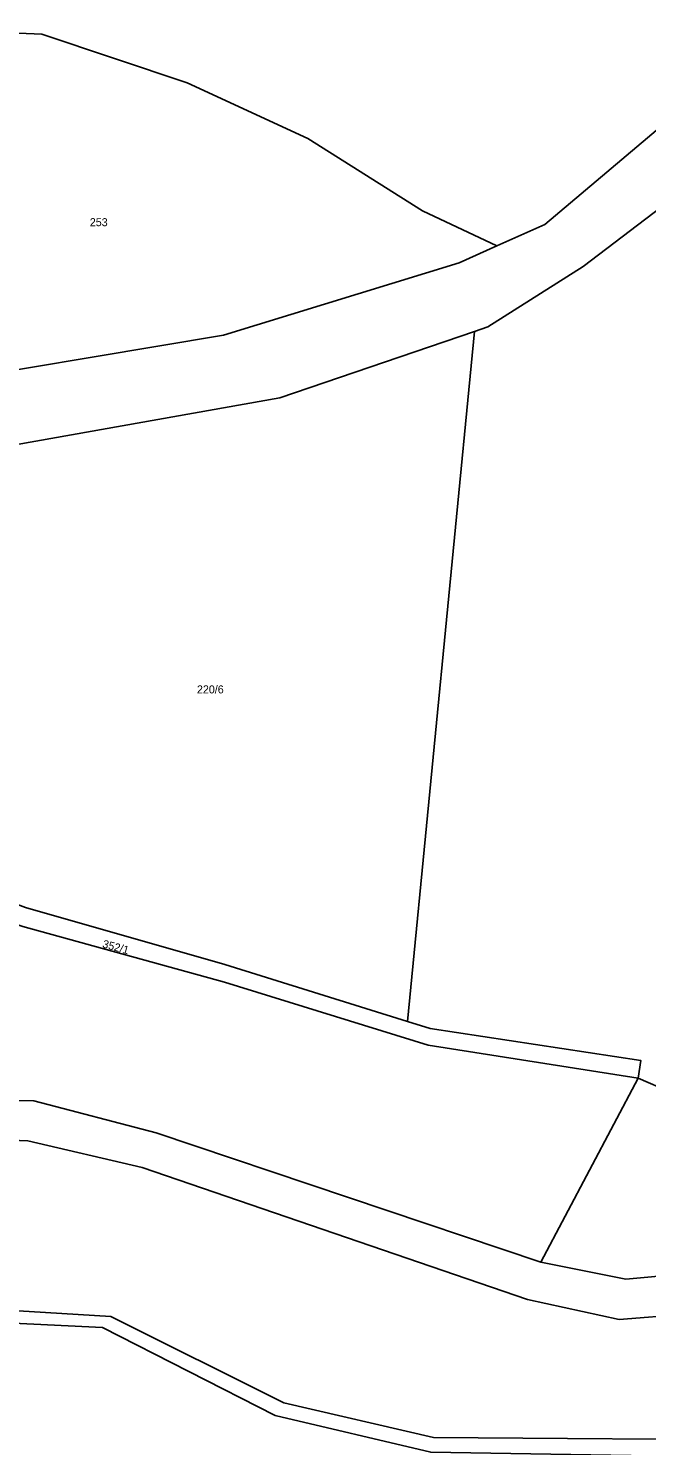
# Model space of a CAD drawing. Extents: x -880531 to -877616, y -1023932 to -1021350.
# Drawn here: x -878561.2 to -878429.8, y -1022509.8 to -1022208.6 of the extents above; entities that cross this region are included whole.
import ezdxf

# ---------------------------------------------------------------- set-up
doc = ezdxf.new("R2010")
doc.units = 0
doc.layers.add('Hranice parcel', color=7, linetype='Continuous')
doc.layers.add('Parcelní čísla', color=7, linetype='Continuous')

msp = doc.modelspace()

# ---------------------------------------------------------------- linework, layer by layer
at = {"layer": 'Hranice parcel'}
for p, q in [((-878466.42, -1022273.02), (-878480.63, -1022419.65)), ((-878452.29, -1022470.77), (-878431.64, -1022431.71))]:
    msp.add_line(p, q, dxfattribs=at)
for points in [[(-878461.63, -1022254.79), (-878477.42, -1022247.38), (-878501.8, -1022232.02), (-878527.45, -1022220.17), (-878558.36, -1022209.87), (-878586.62, -1022208.6)], [(-878421.01, -1022224.59), (-878451.48, -1022250.3), (-878461.63, -1022254.79)], [(-878410.12, -1022233.98), (-878443.28, -1022259.18), (-878463.58, -1022272.05), (-878466.42, -1022273.02)], [(-878589.21, -1022285.43), (-878519.72, -1022273.83), (-878469.66, -1022258.46), (-878461.63, -1022254.79)], [(-878466.42, -1022273.02), (-878507.75, -1022287.12), (-878585.67, -1022300.91), (-878609.56, -1022306.45)], [(-878198.58, -1022353.06), (-878224.68, -1022365.84), (-878269.45, -1022378.84), (-878294.97, -1022391.21), (-878316.58, -1022407.71), (-878347.44, -1022428.86), (-878371.72, -1022441.17), (-878390.58, -1022443.68), (-878411.01, -1022440.6), (-878431.64, -1022431.71)], [(-878575.47, -1022390.32), (-878561.81, -1022395.45), (-878519.45, -1022407.53), (-878480.63, -1022419.65)], [(-878431.64, -1022431.71), (-878476.27, -1022424.65), (-878519.53, -1022411.25), (-878562.4, -1022399.42), (-878575.9, -1022394.81)], [(-878480.63, -1022419.65), (-878475.82, -1022421.15), (-878431.02, -1022427.93), (-878431.64, -1022431.71)], [(-878452.29, -1022470.77), (-878434.2, -1022474.39), (-878410.19, -1022472.17), (-878361.38, -1022456.95), (-878336.49, -1022449.29), (-878323.26, -1022446.51), (-878300.76, -1022445.25), (-878207.33, -1022443.11), (-878169.2, -1022442.13), (-878154.71, -1022440.73), (-878108.69, -1022433.47)], [(-878779.59, -1022496.84), (-878759.93, -1022509.12), (-878743.95, -1022508.49), (-878730.15, -1022504.28), (-878711.96, -1022492.47), (-878672.55, -1022459.82), (-878657.85, -1022450.75), (-878638.42, -1022445.65), (-878606.87, -1022440.92), (-878579.56, -1022436.07), (-878560.03, -1022436.51), (-878534.07, -1022443.31), (-878452.29, -1022470.77)], [(-878108.11, -1022440.58), (-878152.15, -1022446.77), (-878167.86, -1022449.63), (-878217.16, -1022451.24), (-878301.33, -1022453.9), (-878333.67, -1022456.67), (-878366.21, -1022467.52), (-878407.13, -1022480.7), (-878435.64, -1022482.95), (-878455.12, -1022478.73), (-878537.04, -1022450.63), (-878561.34, -1022444.97), (-878578.99, -1022444.28), (-878605.69, -1022449.33), (-878637.81, -1022454.4), (-878653.86, -1022459.64), (-878669.06, -1022467.56), (-878706.56, -1022499.73), (-878724.15, -1022512.39), (-878736.44, -1022518.55), (-878757.9, -1022522.41)], [(-878757.9, -1022522.41), (-878743.38, -1022532.72), (-878730.23, -1022539.4), (-878709.85, -1022535.98), (-878694.32, -1022525.35), (-878670.27, -1022495.13), (-878649.48, -1022475.44), (-878635.27, -1022470.68), (-878614.41, -1022478.04), (-878543.73, -1022482.35), (-878506.92, -1022500.7), (-878475.11, -1022508.02), (-878399.08, -1022508.59), (-878373.94, -1022502.74), (-878346.19, -1022490.2), (-878334.94, -1022490.41), (-878279.22, -1022499.74), (-878220.51, -1022507.42), (-878194.43, -1022507.39), (-878145.84, -1022503.8), (-878124.82, -1022500.78)], [(-878125.35, -1022504.99), (-878146.35, -1022507.21), (-878194.02, -1022510.96), (-878220.76, -1022511.05), (-878280.27, -1022503.97), (-878335.4, -1022493.58), (-878344.86, -1022493.55), (-878371.73, -1022505.4), (-878399.1, -1022512.43), (-878475.7, -1022511.16), (-878508.77, -1022503.35), (-878545.47, -1022484.68), (-878615.6, -1022481.24), (-878635.5, -1022474.3), (-878648.14, -1022478.45), (-878668.08, -1022496.96), (-878691.68, -1022527.88), (-878708.19, -1022539.68), (-878731.2, -1022543.61), (-878748.07, -1022535.1), (-878763.51, -1022523.14)]]:
    msp.add_lwpolyline(points, dxfattribs=at)

# ---------------------------------------------------------------- texts
at = {"layer": 'Parcelní čísla'}
for s, p in [('253', (-878548.16, -1022250.64)), ('220/6', (-878525.39, -1022349.92))]:
    msp.add_text(s, height=1.7, dxfattribs=at).set_placement(p)
msp.add_text('352/1', height=1.7, rotation=345, dxfattribs=at).set_placement((-878545.599, -1022403.891))

doc.saveas('drawing.dxf')
